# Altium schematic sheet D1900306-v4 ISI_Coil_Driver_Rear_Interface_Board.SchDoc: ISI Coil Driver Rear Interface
size C; Date: 05/27/09; DrawnBy: Mohana Mageswaran; Engineer: Mohana Mageswaran; Address1: California institute of Technology; DocumentNumber: D1900306; Revision: v4; SheetNumber: 1; SheetTotal: 1; PageSetup: Record=PageOptions¦CenterHorizontal=True¦CenterVertical=True¦PrintScale=0.69¦XCorrection=1.00¦YCorrection=1.00¦PrintKind=1¦BorderSize=5000000¦LeftOffset=0¦BottomOffset=0¦Orientation=2¦PaperLength=1000¦PaperWidth=1000¦Scale=100¦PaperSource=15¦PrintQuality=600¦MediaType=1¦DitherType=10¦PaperKind=11x17¦PrintScaleMode=1
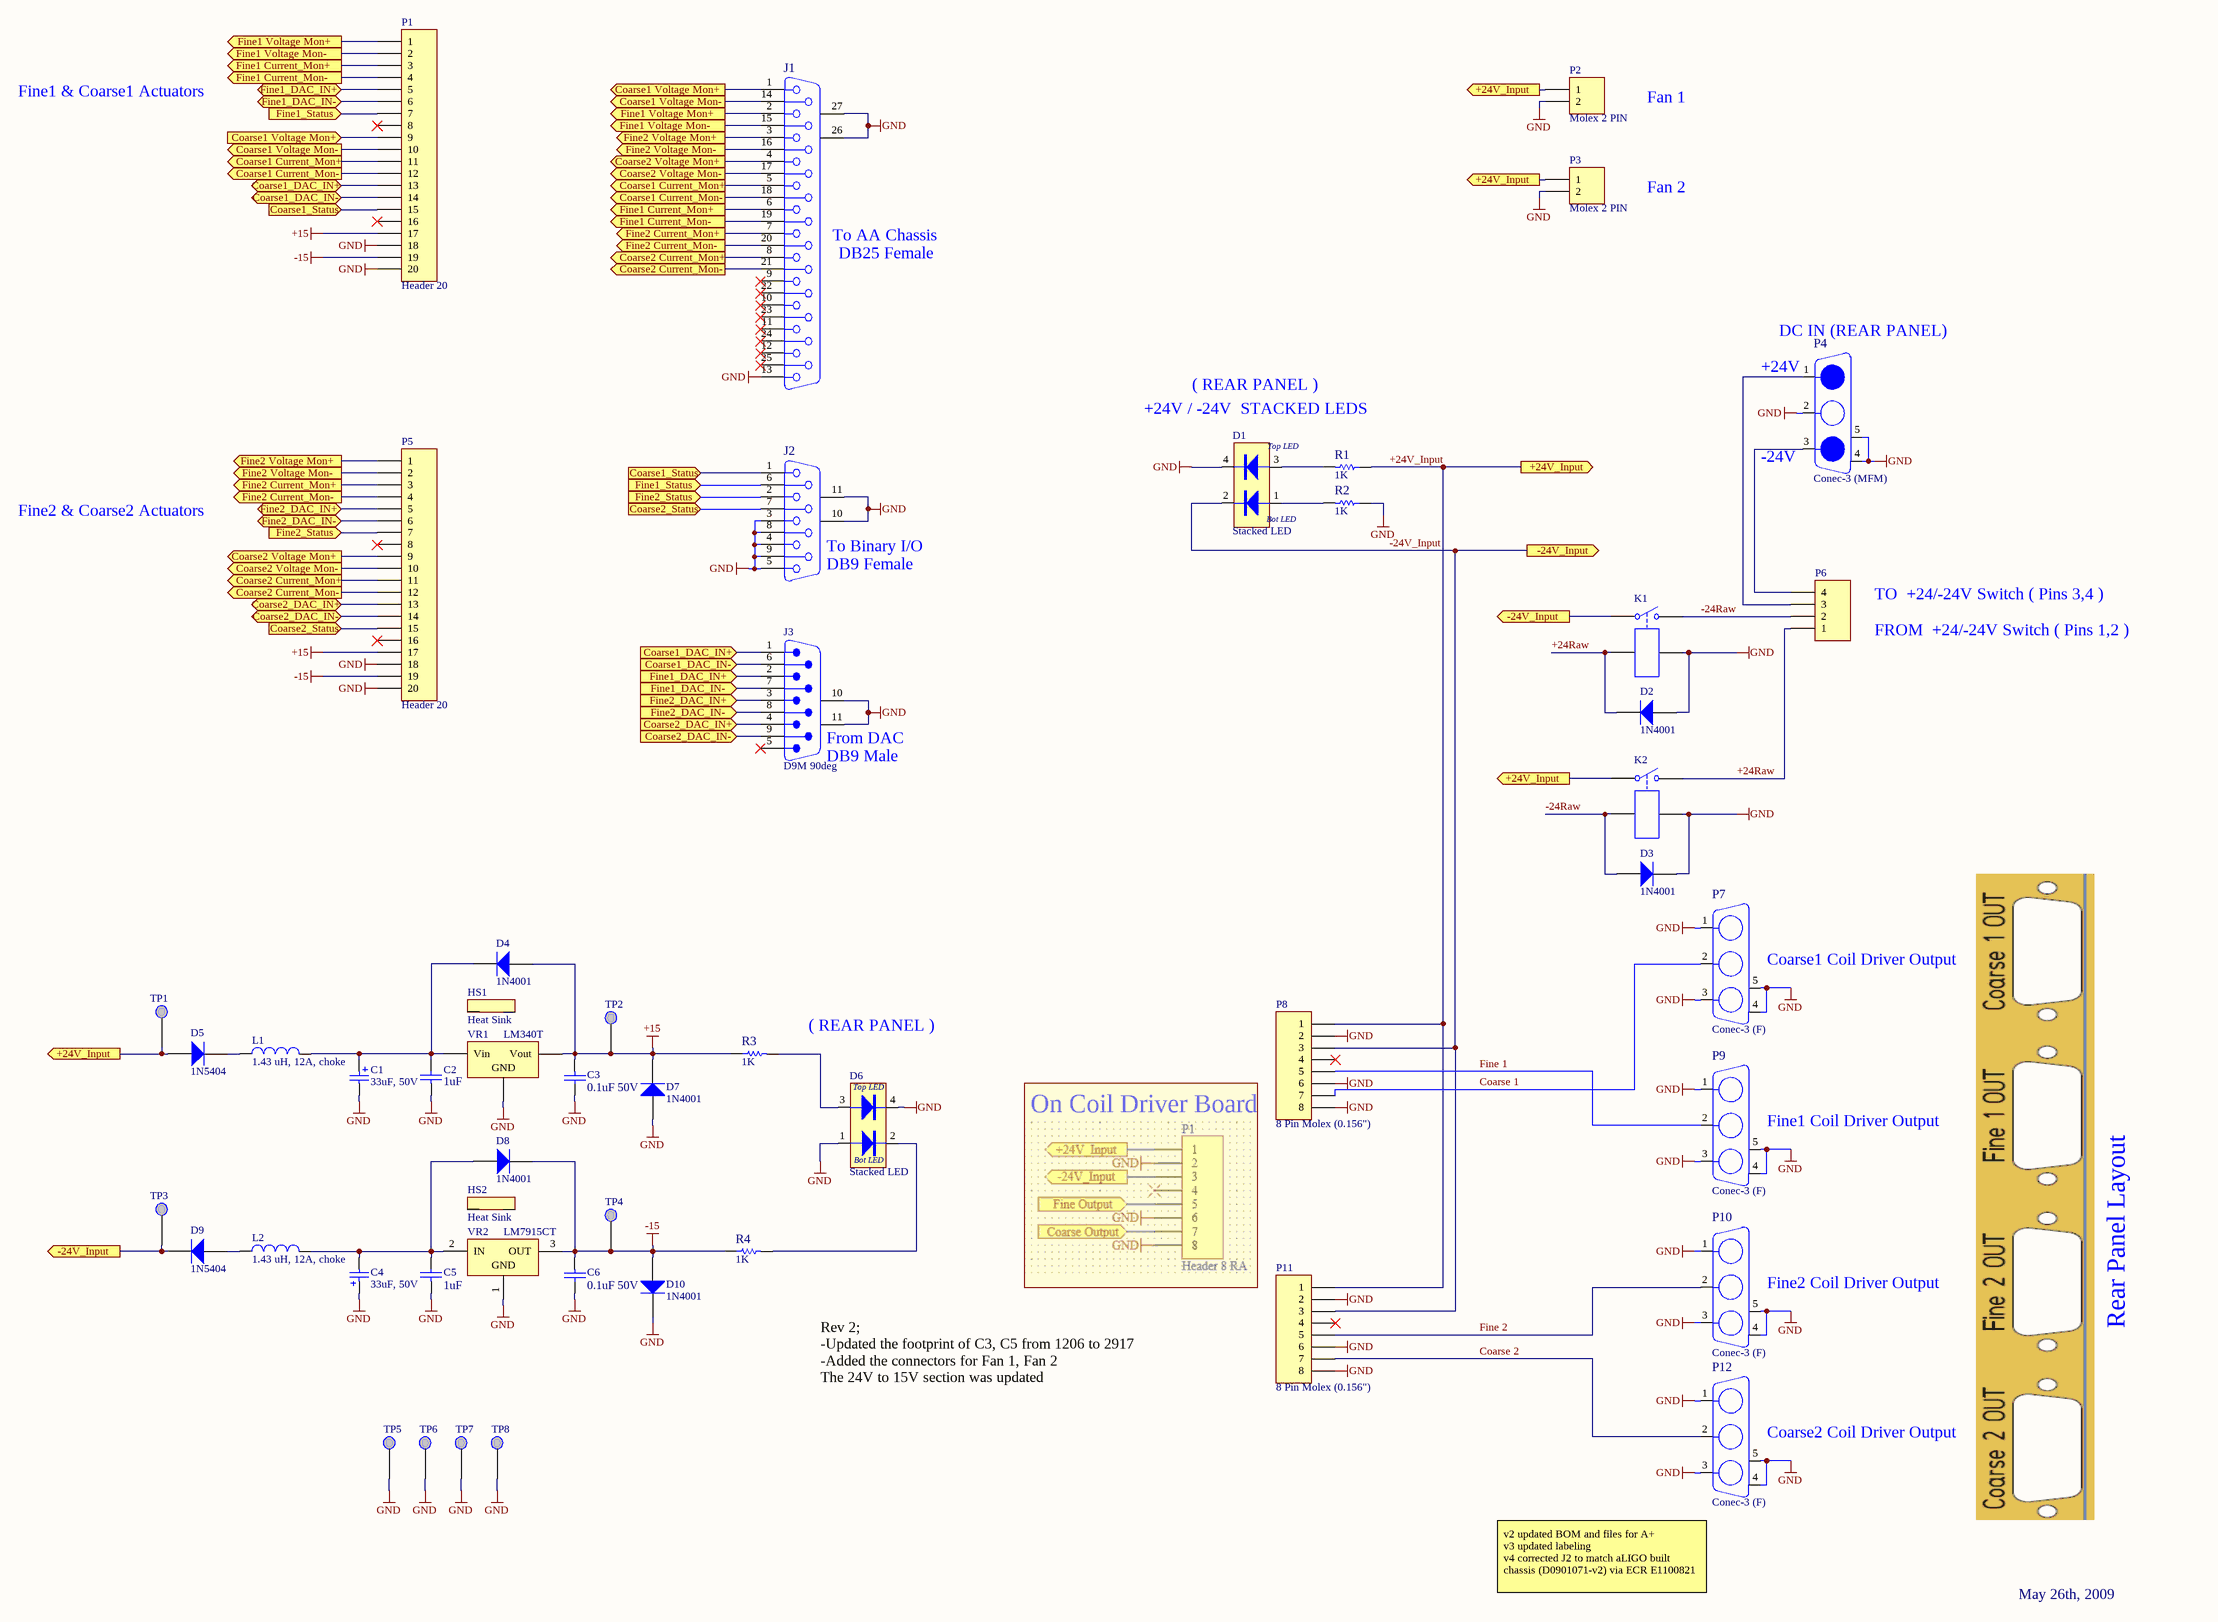
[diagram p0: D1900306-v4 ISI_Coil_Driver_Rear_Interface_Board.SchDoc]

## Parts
C1  33uF, 50V  [T543x]
C2  1uF  [1206 (3216 Metric) CAP]
C3  0.1uF 50V  [1206 (3216 Metric) CAP]
C4  33uF, 50V  [T543x]
C5  1uF  [1206 (3216 Metric) CAP]
C6  0.1uF 50V  [1206 (3216 Metric) CAP]
D1  Stacked LED  [DUAL_LED]
D2  1N4001  [DO-41]
D3  1N4001  [DO-41]
D4  1N4001  [DO-41]
D5  1N5404  [DO-201AD]
D6  Stacked LED  [DUAL_LED]
D7  1N4001  [DO-41]
D8  1N4001  [DO-41]
D9  1N5404  [DO-201AD]
D10  1N4001  [DO-41]
HS1  Heat Sink  [Heat SInk TO-220]
HS2  Heat Sink  [Heat SInk TO-220]
J1  D Connector 25  [DSUB1.385-2H25A]  (value not drawn)
J2  D9F 90deg  [DB9/F/RA]  (value not drawn)
J3  D9M 90deg  [DB9/M/RA]
K1  Relay-SPST  [Panasonic Relay_5A]  (value not drawn)
K2  Relay-SPST  [Panasonic Relay_5A]  (value not drawn)
L1  1.43 uH, 12A, choke  [Power choke]
L2  1.43 uH, 12A, choke  [Power choke]
P1  Header 20  [IDC 20 _Vertical]
P2  Molex 2 PIN  [MOLE_2PIN_0.156]
P3  Molex 2 PIN  [MOLE_2PIN_0.156]
P4  Conec-3 (MFM)  [Conec-3 - (+/-24V M/F/M) PWR IN (10.7mm Tab)]
P5  Header 20  [IDC 20 _Vertical]
P6  Header 4  [4 PIN_MOLEX]  (value not drawn)
P7  Conec-3 (F)  [Conec-3 - (FFF) PWR OUT (10.7mm Tabs)]
P8  8 Pin Molex (0.156")  [8 pin_Molex(0.156)]
P9  Conec-3 (F)  [Conec-3 - (FFF) PWR OUT (10.7mm Tabs)]
P10  Conec-3 (F)  [Conec-3 - (FFF) PWR OUT (10.7mm Tabs)]
P11  8 Pin Molex (0.156")  [8 pin_Molex(0.156)]
P12  Conec-3 (F)  [Conec-3 - (FFF) PWR OUT (10.7mm Tabs)]
R1  1K  [3216[1206]]
R2  1K  [3216[1206]]
R3  1K  [3216[1206]]
R4  1K  [3216[1206]]
TP1  SMT TP  [SMT_TP]  (value not drawn)
TP2  SMT TP  [SMT_TP]  (value not drawn)
TP3  SMT TP  [SMT_TP]  (value not drawn)
TP4  SMT TP  [SMT_TP]  (value not drawn)
TP5  SMT TP  [SMT_TP]  (value not drawn)
TP6  SMT TP  [SMT_TP]  (value not drawn)
TP7  SMT TP  [SMT_TP]  (value not drawn)
TP8  SMT TP  [SMT_TP]  (value not drawn)
VR1  LM340T  [TO-220AB]
VR2  LM7915CT  [TO-220AB]

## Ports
+24V_Input (out), -24V_Input (out), Coarse1 Current_Mon+ (out), Coarse1 Current_Mon- (out), Coarse1 Voltage Mon+ (in), Coarse1 Voltage Mon+ (out), Coarse1 Voltage Mon- (out), Coarse1_DAC_IN+ (bidir), Coarse1_DAC_IN+ (in), Coarse1_DAC_IN- (bidir), Coarse1_DAC_IN- (in), Coarse1_Status (in), Coarse2 Current_Mon+ (out), Coarse2 Current_Mon- (out), Coarse2 Voltage Mon+ (out), Coarse2 Voltage Mon- (out), Coarse2_DAC_IN+ (bidir), Coarse2_DAC_IN+ (in), Coarse2_DAC_IN- (bidir), Coarse2_DAC_IN- (in), Coarse2_Status (in), Fine1 Current_Mon+ (out), Fine1 Current_Mon- (out), Fine1 Voltage Mon+ (out), Fine1 Voltage Mon- (out), Fine1_DAC_IN+ (bidir), Fine1_DAC_IN+ (in), Fine1_DAC_IN- (bidir), Fine1_DAC_IN- (in), Fine1_Status (in), Fine2 Current_Mon+ (out), Fine2 Current_Mon- (out), Fine2 Voltage Mon+ (out), Fine2 Voltage Mon- (out), Fine2_DAC_IN+ (bidir), Fine2_DAC_IN+ (in), Fine2_DAC_IN- (bidir), Fine2_DAC_IN- (in), Fine2_Status (in)

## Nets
+15: C3.1 D4.1(A) D7.2(K) P1.17 P5.17 R3.1 TP2.1 VR1.3(Vout)
-15: C6.1 D8.2(K) D10.1(A) P1.19 P5.19 R4.1 TP4.1 VR2.3(OUT)
GND: C1.2 C2.1 C3.2 C4.1 C5.1 C6.2 D1.4(ANODE) D2.1(A) D3.2(K) D6.1(COM) D6.4(ANODE) D7.1(A) D10.2(K) J1.13 J1.26(MH1) J1.27(MH2) J2.3 J2.4 J2.5 J2.8 J2.9 J2.10(MH1) J2.11(MH2) J3.10(MH1) J3.11(MH2) K1.4 K2.4 P1.18 P1.20 P2.2 P3.2 P4.2 P4.4 P4.5 P5.18 P5.20 P7.1 P7.3 P7.4 P7.5 P8.2 P8.6 P8.8 P9.1 P9.3 P9.4 P9.5 P10.1 P10.3 P10.4 P10.5 P11.2 P11.6 P11.8 P12.1 P12.3 P12.4 P12.5 R2.1 TP5.1 TP6.1 TP7.1 TP8.1 VR1.2(GND) VR2.1(GND)
+24Raw: D2.2(K) K1.3 K2.2 P6.1
+24V_Input: D5.1(A) K2.1 P2.1 P3.1 P8.1 P11.1 R1.1 TP1.1 ; port +24V_Input
-24Raw: D3.1(A) K1.2 K2.3 P6.2
-24V_Input: D1.2(CATHODE) D9.2(K) K1.1 P8.3 P11.3 TP3.1 ; port -24V_Input
Coarse1 Current_Mon+: J1.5 P1.11 ; port Coarse1 Current_Mon+
Coarse1 Current_Mon-: J1.18 P1.12 ; port Coarse1 Current_Mon-
Coarse1 Voltage Mon+: J1.1 P1.9 ; port Coarse1 Voltage Mon+
Coarse1 Voltage Mon-: J1.14 P1.10 ; port Coarse1 Voltage Mon-
Coarse1_DAC_IN+: J3.1 P1.13 ; port Coarse1_DAC_IN+
Coarse1_DAC_IN-: J3.6 P1.14 ; port Coarse1_DAC_IN-
Coarse1_Status: J2.1 P1.15 ; port Coarse1_Status
Coarse2 Current_Mon+: J1.8 P5.11 ; port Coarse2 Current_Mon+
Coarse2 Current_Mon-: J1.21 P5.12 ; port Coarse2 Current_Mon-
Coarse2 Voltage Mon+: J1.4 P5.9 ; port Coarse2 Voltage Mon+
Coarse2 Voltage Mon-: J1.17 P5.10 ; port Coarse2 Voltage Mon-
Coarse2_DAC_IN+: J3.4 P5.13 ; port Coarse2_DAC_IN+
Coarse2_DAC_IN-: J3.9 P5.14 ; port Coarse2_DAC_IN-
Coarse2_Status: J2.7 P5.15 ; port Coarse2_Status
Coarse 1: P7.2 P8.7
Coarse 2: P11.7 P12.2
Fine1 Current_Mon+: J1.6 P1.3 ; port Fine1 Current_Mon+
Fine1 Current_Mon-: J1.19 P1.4 ; port Fine1 Current_Mon-
Fine1 Voltage Mon+: J1.2 P1.1 ; port Fine1 Voltage Mon+
Fine1 Voltage Mon-: J1.15 P1.2 ; port Fine1 Voltage Mon-
Fine1_DAC_IN+: J3.2 P1.5 ; port Fine1_DAC_IN+
Fine1_DAC_IN-: J3.7 P1.6 ; port Fine1_DAC_IN-
Fine1_Status: J2.6 P1.7 ; port Fine1_Status
Fine2 Current_Mon+: J1.7 P5.3 ; port Fine2 Current_Mon+
Fine2 Current_Mon-: J1.20 P5.4 ; port Fine2 Current_Mon-
Fine2 Voltage Mon+: J1.3 P5.1 ; port Fine2 Voltage Mon+
Fine2 Voltage Mon-: J1.16 P5.2 ; port Fine2 Voltage Mon-
Fine2_DAC_IN+: J3.3 P5.5 ; port Fine2_DAC_IN+
Fine2_DAC_IN-: J3.8 P5.6 ; port Fine2_DAC_IN-
Fine2_Status: J2.2 P5.7 ; port Fine2_Status
Fine 1: P8.5 P9.2
Fine 2: P10.2 P11.5
NetC1_1: C1.1 C2.2 D4.2(K) L1.2 VR1.1(Vin)
NetC4_2: C4.2 C5.2 D8.1(A) L2.2 VR2.2(IN)
NetD1_1: D1.1(COM) R2.2
NetD1_3: D1.3(ANODE) R1.2
NetD5_2: D5.2(K) L1.1
NetD6_2: D6.2(CATHODE) R4.2
NetD6_3: D6.3(ANODE) R3.2
NetD9_1: D9.1(A) L2.1
NetP4_1: P4.1 P6.3
NetP4_3: P4.3 P6.4

Not connected (* = marked no-connect by the designer): HS1 1(GND) 2(GND); HS2 1(GND) 2(GND); J1 9* 10* 11* 12* 22* 23* 24* 25*; J3 5*; P1 8* 16*; P5 8* 16*; P8 4*; P11 4*

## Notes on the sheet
- Fine1 & Coarse1 Actuators
- Fan 1
- Fan 2
- (near J1) To AA Chassis
- (near J1) DB25 Female
- (near P4) DC IN (REAR PANEL)
- +24V / -24V  STACKED LEDS
- ( REAR PANEL )
- (near P4) +24V
- (near P4) -24V
- Fine2 & Coarse2 Actuators
- (near J2) To Binary I/O
- (near J2) DB9 Female
- FROM  +24/-24V Switch ( Pins 1,2 )
- TO  +24/-24V Switch ( Pins 3,4 )
- (near J3) From DAC
- (near J3) DB9 Male
- (near P7) Coarse1 Coil Driver Output
- (near P8) On Coil Driver Board
- (near P9) Fine1 Coil Driver Output
- (near P10) Fine2 Coil Driver Output
- Rear Panel Layout
- Rev 2;
  -Updated the footprint of C3, C5 from 1206 to 2917
  -Added the connectors for Fan 1, Fan 2
  The 24V to 15V section was updated
- (near P12) Coarse2 Coil Driver Output
- (near P12) v2 updated BOM and files for A+
  v3 updated labeling
  v4 corrected J2 to match aLIGO built chassis (D0901071-v2) via ECR E1100821
- May 26th, 2009

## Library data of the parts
C1 C4 = T543X: 33µF Molded Tantalum Polymer Capacitor 50V 2917 (7343 Metric) 40mOhm @ 100kHz; Manufacturer: KEMET; Manufacturer Part Number: T543X336M050AHE040; Tolerance: 20%; ESR (Equivalent Series Resistance): 40mR; Leakage Current: 165uA; Polarity: Polar; Dissipation Factor: 10%
C2 C5 = CAP: 1µF ±10% 25V Ceramic Capacitor X7R 1206 (3216 Metric); Manufacturer: TDK-Lambda; Manufacturer Part Number: C1206C105K3RACTU
C3 C6 = 0.1uF 50V: 0.1µF ±5% 50V Ceramic Capacitor X7R 1206 (3216 Metric); Manufacturer: KEMET; Manufacturer Part Number: C1206C104J5RACTU; Capacitance: 100nF
D1 D6 = Dual Stacked LED: Dual Green LED; Manufacturer: Lumex; Manufacturer Part Number: SSF-LXH240GGD; Voltage Rating: 2.2V; Number of Contacts: 2; Viewing Angle: 60°; Lens Style: Diffused,Tinted,Round,Colored; Luminous Intensity: 40mcd; Forward Current: 25mA; Wavelength: 565nm
D2-D4 D7 D8 D10 = Diode 1N4001: 1 Amp General Purpose Rectifier; Manufacturer: Diodes; Manufacturer Part Number: 1N4001G-T; Max Surge Current: 30A; Recovery Time: 2us; Forward Voltage: 1V; Peak Reverse Current: 5uA; Reverse Voltage (DC): 50V; Average Rectified Current: 1A; Element Configuration: Single; Polarity: Standard; Capacitance: 8pF
D5 D9 = Diode 1N5404: Diode Standard 400V 3A Through Hole DO-201AD; Manufacturer: Vishay Semiconductors; Manufacturer Part Number: 1N5404-E3/54; Peak Reverse Current: 5uA; Max Surge Current: 200A; Forward Voltage: 1.2V; Element Configuration: Single; Capacitance: 30pF
HS1 HS2 = Heat Sink: Heat Sink TO-220 Aluminum 8.0W @ 80°C Board Level, Vertical; Manufacturer: Ohmite; Manufacturer Part Number: EA-T220-38E; Shape: Fins,Rectangular; Thermal Resistance @ Forced Air Flow (100 LFM): 4°C/W; Natural Thermal Resistance: 10.4°C/W
J1 = D Connector 25: 25 Position D-Sub Receptacle, Female Sockets Connector; Manufacturer: TE Connectivity; Manufacturer Part Number: 57478464; PackageDocument: U; Positions: 25; Plating: Tin; Body Material: Metal; Voltage Rating: 125V; Current Rating: 6A; Number of Ports: 1; Mating Connector Lock: Yes (With); PCB Mount Retention: With; PCB Mounting Orientation: Right Angle; Preloaded: Yes; Sealable: No (Without); Pitch: 0.109inch; PCB Thickness: 1.57mm; Contact Post Length: 0.125inch; Hole Diameter: 3.18mm; Approvals: UL,CSA
J2 = DB9/F/RA: Receptacle Assembly, 9 Position, Right Angle; Manufacturer: AMP - TE CONNECTIVITY; Manufacturer Part Number: 5747844-4
J3 = DB9/M/RA: 9 Position D-Sub Plug, Male Pins Connector; Manufacturer: TE Connectivity; Manufacturer Part Number: 5747840-3; Plating: Tin; Body Material: Metal,Steel; Voltage Rating: 125V; Current Rating: 6A; Number of Positions: 9; Number of Ports: 1; Mating Connector Lock: Yes (With); PCB Mount Retention: With; Preloaded: Yes; Sealable: No (Without); Circuit Application: Signal; Connector System: Board-to-Board; Pitch: 0.108inch; PCB Thickness: 1.57mm; Contact Post Length: 0.125inch; Row Spacing: 2.84mm; Approvals: CSA,UL
K1 K2 = Relay-SPST: Single-Pole Single-Throw Relay; Manufacturer: Panasonic; Manufacturer Part Number: JQ1A-24V-F; Voltage Rating (AC): 250V; Power Rating: 200mW; Max Voltage Rating (DC): 110V; Contact Current Rating: 5A; Throw Configuration: SPST; Coil Resistance: 2.88kR; Coil Current: 8.3mA; Operate Time: 20ms; Release Time: 10ms; Coil Voltage (DC): 24V; Coil Type: Non-Latching; Relay Type: General Purpose
L1 L2 = INDUCTOR: 1mH Shielded  Inductor 550mA 1.82Ohm Max Nonstandard; Manufacturer: Sumida; Manufacturer Part Number: CDRH127NP-102MC; Core Material: Ferrite; Tolerance: 20%; DC Resistance (DCR): 1.82R; Test Frequency: 1kHz
P1 P5 = Header 20: Header, 20-Pin; Manufacturer: Amphenol FCI; Manufacturer Part Number: 71918-120LF; Mating Cycles: 250; Number of Poles: 20; Max Voltage Rating (AC): 1.5kV; Insulation Resistance: 100GR; Gender: Male; Connector Type: Male Pin; Current Rating: 1A; Pitch: 2.54mm; Row Spacing: 0.1inch; Hole Diameter: 1mm; Contact Post Length: 2.9mm; Approvals: UL,CSA
P2 P3 = Header 2H (3.96mm): Connector Header Through Hole 2 position 0.156" (3.96mm); Number of Positions: 2; Gender: Male; Contact Resistance: 6mR; Current Rating: 7A; Voltage Rating: 250V; Insulation Resistance: 50GR; Glow Wire Compliant: Non-compliant
P4 = +/-24 Conec-3 (MFM) (10.7mm Tabs): 3 (Power) Position D-Sub, Combo Plug, 2 Male Pins, 1 Female Pin Connector (10.7mm Tabs) / Connec PN 303W3CPXX56K40X
P6 = Header 4: Header, 4-Pin; Manufacturer: Molex; Number of Positions: 4; Gender: Male; Contact Resistance: 6mR; Voltage Rating: 250V; Current Rating: 7A; Insulation Resistance: 50GR; Pitch: 3.96mm; Approvals: UL,CSA,TUV; Glow Wire Compliant: Non-compliant
P7 P9 P10 P12 = Conec-3 (FFF) (10.7mm Tabs): D-Sub Mixed Contact Connectors 3W3 M R/A .370 20 AMP POWER; Manufacturer Part Number: 3003W3SXX56K40X
P8 P11 = Header 8: Connector Header Through Hole 8 position 0.156" (3.96mm); Number of Positions: 8; Gender: Male; Connector Type: Male Pin; Contact Resistance: 6mR; Max Voltage Rating (AC): 250V
R1-R4 = Res Semi: 1 kOhms ±0.5% 0.25W, 1/4W Chip Resistor 1206 (3216 Metric)  Thin Film; Manufacturer: Yageo; Manufacturer Part Number: RT1206DRE071KL; Resistance: 1kR; Max Power Dissipation: 250mW; Temperature Coefficient: 50ppm/°C; Voltage Rating (DC): 200V
TP1-TP8 = SMT TP: PC Test Point, Miniature Phosphor Bronze, Silver Plating Surface Mount Mounting Type; Manufacturer: Keystone Electronics; Manufacturer Part Number: 5019
VR1 = LM340T: Linear Voltage Regulator IC Positive Fixed 1 Output  1.5A TO-220-3; Manufacturer: TI National Semiconductor; Manufacturer Part Number: LM340T-15/NOPB; Dropout Voltage: 2V; Number of Outputs: 1; Output Current: 1A; Max Input Voltage: 35V; Output Voltage: 15V; Max Supply Voltage: 30V; Min Supply Voltage: 17.5V; Min Input Voltage: 17.7V; Quiescent Current: 8mA; Accuracy: 2%; Tolerance: 5%; Power Supply Rejection Ratio (PSRR): 80dB
VR2 = LM7915CT: Linear Voltage Regulator IC Negative Fixed 1 Output  1.5A TO-220-3; Manufacturer: TI National Semiconductor; Manufacturer Part Number: LM7915CT/NOPB; Number of Outputs: 1; Output Voltage: -15V; Max Input Voltage: -23V; Min Input Voltage: -17.5V; Dropout Voltage: 1.1V; Quiescent Current: 3mA; Accuracy: 4%; Min Output Voltage: -14.4V; Max Output Voltage: -15.6V; Tolerance: 5%; Power Supply Rejection Ratio (PSRR): 70dB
